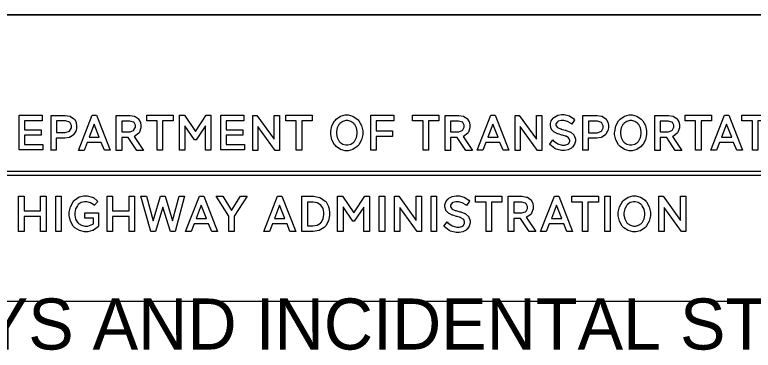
# Model space of a CAD drawing. Extents: x -27.4 to -18.9, y -4.2 to 6.8.
# Drawn here: x -21.647 to -20.305, y -3.032 to -2.423 of the extents above; entities that cross this region are included whole.
import ezdxf

# ---------------------------------------------------------------- set-up
doc = ezdxf.new("R2010")
doc.units = 0
for name, color, linetype in [('BORD-LINE', 7, 'Continuous'), ('MSHA-LOGO', 7, 'Continuous'), ('TTLB-TEXT', 7, 'Continuous'), ('USER-LINE', 7, 'Continuous')]:
    doc.layers.add(name, color=color, linetype=linetype)

msp = doc.modelspace()

# ---------------------------------------------------------------- linework, layer by layer
at = {"layer": 'BORD-LINE'}
msp.add_line((-19.2324, -2.4232), (-23.7053, -2.4232), dxfattribs=at)
at = {"layer": 'MSHA-LOGO'}
for points in [[(-21.639, -2.6056), (-21.5968, -2.6056), (-21.5968, -2.6157), (-21.6292, -2.6157), (-21.6292, -2.6319), (-21.5988, -2.6319), (-21.5988, -2.6417), (-21.6292, -2.6417), (-21.6292, -2.6585), (-21.5958, -2.6585), (-21.5958, -2.6687), (-21.639, -2.6687)], [(-21.5808, -2.6694), (-21.5808, -2.6059), (-21.5579, -2.6059), (-21.555, -2.6059), (-21.5469, -2.6073), (-21.5461, -2.6075), (-21.5453, -2.6078), (-21.5393, -2.612), (-21.5389, -2.6125), (-21.5385, -2.6129), (-21.5355, -2.6185), (-21.5353, -2.619), (-21.5352, -2.6196), (-21.5343, -2.6248), (-21.5343, -2.6266), (-21.5343, -2.6285), (-21.5354, -2.6336), (-21.5356, -2.6342), (-21.5359, -2.6347), (-21.5392, -2.6402), (-21.5396, -2.6407), (-21.54, -2.6412), (-21.5463, -2.6453), (-21.5471, -2.6457), (-21.5479, -2.646), (-21.5556, -2.6473), (-21.5582, -2.6473), (-21.5713, -2.6473), (-21.5713, -2.669), (-21.5808, -2.669)], [(-21.5707, -2.6157), (-21.5707, -2.6371), (-21.5576, -2.6371), (-21.555, -2.6371), (-21.5473, -2.6344), (-21.5438, -2.6283), (-21.5438, -2.6263), (-21.5438, -2.6243), (-21.547, -2.6184), (-21.5544, -2.6157), (-21.5569, -2.6157)], [(-21.5059, -2.6056), (-21.4983, -2.6056), (-21.4734, -2.669), (-21.4839, -2.669), (-21.4895, -2.6552), (-21.5153, -2.6552), (-21.5209, -2.6694), (-21.531, -2.6694)], [(-21.4623, -2.6694), (-21.4623, -2.6059), (-21.4401, -2.6059), (-21.4373, -2.6059), (-21.4298, -2.6073), (-21.4289, -2.6075), (-21.4282, -2.6078), (-21.4225, -2.6116), (-21.4221, -2.6121), (-21.4217, -2.6126), (-21.4187, -2.6178), (-21.4185, -2.6184), (-21.4183, -2.619), (-21.4175, -2.6242), (-21.4175, -2.6259), (-21.4175, -2.6288), (-21.4202, -2.6366), (-21.4208, -2.6375), (-21.4213, -2.6383), (-21.429, -2.644), (-21.4299, -2.6444), (-21.4129, -2.6697), (-21.425, -2.6697), (-21.4404, -2.6463), (-21.4525, -2.6463), (-21.4525, -2.6697), (-21.4623, -2.6697)], [(-21.4522, -2.6161), (-21.4522, -2.6355), (-21.4394, -2.6355), (-21.4372, -2.6355), (-21.4312, -2.6333), (-21.4306, -2.6328), (-21.4301, -2.6324), (-21.4273, -2.6271), (-21.4273, -2.6253), (-21.4273, -2.6236), (-21.4298, -2.6188), (-21.4303, -2.6184), (-21.4308, -2.618), (-21.4375, -2.6161), (-21.4398, -2.6161)], [(-21.407, -2.6056), (-21.3589, -2.6056), (-21.3589, -2.6157), (-21.3782, -2.6157), (-21.3782, -2.669), (-21.388, -2.669), (-21.388, -2.6157), (-21.407, -2.6157)], [(-21.3475, -2.6056), (-21.3386, -2.6056), (-21.3183, -2.6352), (-21.2987, -2.6056), (-21.2902, -2.6056), (-21.2902, -2.669), (-21.3, -2.669), (-21.3, -2.625), (-21.3174, -2.6503), (-21.32, -2.6503), (-21.3376, -2.625), (-21.3376, -2.669), (-21.3475, -2.669)], [(-21.2725, -2.6056), (-21.2303, -2.6056), (-21.2303, -2.6157), (-21.2627, -2.6157), (-21.2627, -2.6319), (-21.2323, -2.6319), (-21.2323, -2.6417), (-21.2627, -2.6417), (-21.2627, -2.6585), (-21.2293, -2.6585), (-21.2293, -2.6687), (-21.2725, -2.6687)], [(-21.1734, -2.6694), (-21.2048, -2.6259), (-21.2048, -2.6694), (-21.2143, -2.6694), (-21.2143, -2.6059), (-21.2067, -2.6059), (-21.1753, -2.6493), (-21.1753, -2.6059), (-21.1658, -2.6059), (-21.1658, -2.6694)], [(-21.1544, -2.6056), (-21.1063, -2.6056), (-21.1063, -2.6157), (-21.1253, -2.6157), (-21.1253, -2.669), (-21.1351, -2.669), (-21.1351, -2.6157), (-21.1541, -2.6157), (-21.1541, -2.6056)], [(-21.0641, -2.6144), (-21.0627, -2.6129), (-21.0548, -2.6073), (-21.0463, -2.6049), (-21.0435, -2.6049), (-21.0407, -2.6049), (-21.0322, -2.6071), (-21.0242, -2.6125), (-21.0228, -2.6141), (-21.0215, -2.6156), (-21.0165, -2.6245), (-21.0143, -2.6342), (-21.0143, -2.6374), (-21.0143, -2.6406), (-21.0165, -2.6502), (-21.0215, -2.6592), (-21.0228, -2.6608), (-21.0242, -2.6624), (-21.0322, -2.6677), (-21.0407, -2.67), (-21.0435, -2.67), (-21.0463, -2.67), (-21.0548, -2.6677), (-21.0627, -2.6624), (-21.0641, -2.6608), (-21.0655, -2.6592), (-21.0704, -2.6504), (-21.0726, -2.6407), (-21.0726, -2.6374), (-21.0726, -2.6343), (-21.0704, -2.6248), (-21.0655, -2.616)], [(-21.0566, -2.6532), (-21.0557, -2.6543), (-21.0505, -2.658), (-21.045, -2.6595), (-21.0431, -2.6595), (-21.0413, -2.6595), (-21.0358, -2.658), (-21.0306, -2.6543), (-21.0297, -2.6532), (-21.0288, -2.6522), (-21.0256, -2.6463), (-21.0242, -2.6397), (-21.0242, -2.6374), (-21.0242, -2.6352), (-21.0256, -2.6285), (-21.0288, -2.6226), (-21.0297, -2.6217), (-21.0306, -2.6206), (-21.0358, -2.6169), (-21.0413, -2.6154), (-21.0431, -2.6154), (-21.045, -2.6154), (-21.0505, -2.6169), (-21.0557, -2.6206), (-21.0566, -2.6217), (-21.0575, -2.6226), (-21.0607, -2.6285), (-21.0621, -2.6352), (-21.0621, -2.6374), (-21.0621, -2.6397), (-21.0608, -2.6463), (-21.0576, -2.6522)], [(-20.9996, -2.6055), (-20.9577, -2.6055), (-20.9577, -2.6157), (-20.9898, -2.6157), (-20.9898, -2.6338), (-20.96, -2.6338), (-20.96, -2.644), (-20.9898, -2.644), (-20.9898, -2.669), (-20.9996, -2.669)], [(-20.924, -2.6055), (-20.8759, -2.6055), (-20.8759, -2.6157), (-20.8949, -2.6157), (-20.8949, -2.669), (-20.9047, -2.669), (-20.9047, -2.6157), (-20.9237, -2.6157), (-20.9237, -2.6055)], [(-20.8645, -2.6694), (-20.8645, -2.6059), (-20.8422, -2.6059), (-20.8394, -2.6059), (-20.8319, -2.6073), (-20.8311, -2.6075), (-20.8304, -2.6078), (-20.8246, -2.6116), (-20.8242, -2.6121), (-20.8238, -2.6126), (-20.8209, -2.6178), (-20.8206, -2.6184), (-20.8204, -2.6189), (-20.8196, -2.6242), (-20.8196, -2.6259), (-20.8196, -2.6288), (-20.8223, -2.6366), (-20.8229, -2.6374), (-20.8235, -2.6383), (-20.8311, -2.644), (-20.8321, -2.6444), (-20.815, -2.6697), (-20.8271, -2.6697), (-20.8425, -2.6463), (-20.8546, -2.6463), (-20.8546, -2.6697), (-20.8645, -2.6697)], [(-20.8546, -2.6161), (-20.8546, -2.6355), (-20.8419, -2.6355), (-20.8397, -2.6355), (-20.8336, -2.6333), (-20.833, -2.6329), (-20.8326, -2.6324), (-20.8298, -2.6271), (-20.8298, -2.6253), (-20.8298, -2.6235), (-20.8322, -2.6188), (-20.8327, -2.6184), (-20.8332, -2.618), (-20.84, -2.6161), (-20.8422, -2.6161)], [(-20.7813, -2.6055), (-20.7738, -2.6055), (-20.7489, -2.669), (-20.7594, -2.669), (-20.765, -2.6549), (-20.7905, -2.6549), (-20.7961, -2.669), (-20.8062, -2.669)], [(-20.6966, -2.6694), (-20.728, -2.6259), (-20.728, -2.6694), (-20.7375, -2.6694), (-20.7375, -2.6059), (-20.73, -2.6059), (-20.6985, -2.6493), (-20.6985, -2.6059), (-20.6891, -2.6059), (-20.6891, -2.6694)], [(-20.6403, -2.647), (-20.6406, -2.6466), (-20.6447, -2.6439), (-20.6452, -2.6437), (-20.6457, -2.6435), (-20.6514, -2.6419), (-20.6521, -2.6417), (-20.6527, -2.6416), (-20.659, -2.6397), (-20.6596, -2.6394), (-20.6603, -2.6392), (-20.666, -2.6365), (-20.6665, -2.6361), (-20.667, -2.6358), (-20.6711, -2.6314), (-20.6714, -2.6309), (-20.6717, -2.6303), (-20.6733, -2.6245), (-20.6733, -2.6226), (-20.6733, -2.6209), (-20.6718, -2.6157), (-20.6682, -2.6107), (-20.6671, -2.6098), (-20.6661, -2.6089), (-20.66, -2.6058), (-20.6533, -2.6045), (-20.6511, -2.6045), (-20.648, -2.6045), (-20.6386, -2.6068), (-20.6305, -2.6122), (-20.6292, -2.6138), (-20.6344, -2.6217), (-20.6356, -2.6206), (-20.6423, -2.6168), (-20.6491, -2.6151), (-20.6514, -2.6151), (-20.6535, -2.6151), (-20.6594, -2.6167), (-20.6599, -2.6171), (-20.6605, -2.6174), (-20.6632, -2.6213), (-20.6632, -2.6226), (-20.6632, -2.6239), (-20.661, -2.6272), (-20.6606, -2.6276), (-20.6602, -2.6279), (-20.6547, -2.6304), (-20.654, -2.6305), (-20.6534, -2.6307), (-20.6463, -2.6326), (-20.6455, -2.6329), (-20.6448, -2.6331), (-20.6377, -2.6358), (-20.637, -2.6361), (-20.6364, -2.6365), (-20.6309, -2.6411), (-20.6305, -2.6417), (-20.6301, -2.6424), (-20.6279, -2.6488), (-20.6279, -2.6509), (-20.6279, -2.6528), (-20.6294, -2.6584), (-20.633, -2.6635), (-20.6341, -2.6644), (-20.6351, -2.6653), (-20.6412, -2.6684), (-20.6474, -2.6697), (-20.6495, -2.6697), (-20.6531, -2.6697), (-20.6627, -2.667), (-20.6639, -2.6664), (-20.665, -2.6658), (-20.674, -2.659), (-20.6746, -2.6582), (-20.6688, -2.6506), (-20.6675, -2.6521), (-20.6599, -2.6574), (-20.6516, -2.6598), (-20.6488, -2.6598), (-20.6468, -2.6598), (-20.6414, -2.6582), (-20.641, -2.6578), (-20.6405, -2.6575), (-20.638, -2.6535), (-20.638, -2.6522), (-20.6381, -2.6517), (-20.64, -2.6473)], [(-20.6141, -2.6694), (-20.6141, -2.6059), (-20.5912, -2.6059), (-20.5883, -2.6059), (-20.5802, -2.6073), (-20.5794, -2.6075), (-20.5786, -2.6078), (-20.5726, -2.6119), (-20.5722, -2.6124), (-20.5718, -2.6129), (-20.5688, -2.6184), (-20.5686, -2.619), (-20.5685, -2.6196), (-20.5676, -2.6248), (-20.5676, -2.6266), (-20.5676, -2.6285), (-20.5687, -2.6336), (-20.569, -2.6342), (-20.5692, -2.6347), (-20.5725, -2.6402), (-20.5729, -2.6407), (-20.5733, -2.6412), (-20.5796, -2.6453), (-20.5804, -2.6457), (-20.5812, -2.646), (-20.589, -2.6473), (-20.5915, -2.6473), (-20.6046, -2.6473), (-20.6046, -2.669), (-20.6141, -2.669)], [(-20.604, -2.6161), (-20.604, -2.6374), (-20.5909, -2.6374), (-20.5883, -2.6374), (-20.5806, -2.6347), (-20.5771, -2.6286), (-20.5771, -2.6266), (-20.5771, -2.6246), (-20.5804, -2.6187), (-20.5878, -2.6161), (-20.5902, -2.6161)], [(-20.548, -2.6144), (-20.5466, -2.6129), (-20.5387, -2.6073), (-20.5302, -2.6049), (-20.5274, -2.6049), (-20.5246, -2.6049), (-20.5161, -2.6071), (-20.5082, -2.6125), (-20.5068, -2.6141), (-20.5054, -2.6156), (-20.5004, -2.6245), (-20.4983, -2.6342), (-20.4983, -2.6374), (-20.4983, -2.6406), (-20.5004, -2.6502), (-20.5054, -2.6592), (-20.5068, -2.6608), (-20.5082, -2.6624), (-20.5161, -2.6677), (-20.5246, -2.67), (-20.5274, -2.67), (-20.5302, -2.67), (-20.5387, -2.6677), (-20.5466, -2.6624), (-20.548, -2.6608), (-20.5494, -2.6592), (-20.5544, -2.6504), (-20.5565, -2.6407), (-20.5565, -2.6374), (-20.5564, -2.6351), (-20.5542, -2.6248), (-20.5494, -2.616)], [(-20.5405, -2.6532), (-20.5396, -2.6543), (-20.5344, -2.658), (-20.5289, -2.6595), (-20.5271, -2.6595), (-20.5252, -2.6595), (-20.5197, -2.658), (-20.5146, -2.6543), (-20.5137, -2.6532), (-20.5128, -2.6522), (-20.5095, -2.6463), (-20.5081, -2.6397), (-20.5081, -2.6374), (-20.5081, -2.6352), (-20.5095, -2.6285), (-20.5128, -2.6226), (-20.5137, -2.6217), (-20.5146, -2.6206), (-20.5197, -2.6169), (-20.5252, -2.6154), (-20.5271, -2.6154), (-20.5289, -2.6154), (-20.5343, -2.6169), (-20.5395, -2.6206), (-20.5405, -2.6217), (-20.5414, -2.6226), (-20.5446, -2.6285), (-20.5461, -2.6352), (-20.5461, -2.6374), (-20.5461, -2.6397), (-20.5448, -2.6463), (-20.5415, -2.6522)], [(-20.4835, -2.6694), (-20.4835, -2.6059), (-20.4613, -2.6059), (-20.4585, -2.6059), (-20.451, -2.6073), (-20.4502, -2.6075), (-20.4494, -2.6078), (-20.4437, -2.6116), (-20.4433, -2.6121), (-20.4429, -2.6126), (-20.4399, -2.6178), (-20.4397, -2.6184), (-20.4395, -2.6189), (-20.4387, -2.6242), (-20.4387, -2.6259), (-20.4387, -2.6288), (-20.4414, -2.6366), (-20.442, -2.6374), (-20.4426, -2.6383), (-20.4502, -2.644), (-20.4511, -2.6444), (-20.4341, -2.6697), (-20.4462, -2.6697), (-20.4616, -2.6463), (-20.4737, -2.6463), (-20.4737, -2.6697), (-20.4835, -2.6697)], [(-20.4737, -2.6161), (-20.4737, -2.6355), (-20.461, -2.6355), (-20.4588, -2.6355), (-20.4527, -2.6333), (-20.4521, -2.6329), (-20.4516, -2.6324), (-20.4488, -2.6271), (-20.4488, -2.6253), (-20.4488, -2.6235), (-20.4513, -2.6188), (-20.4518, -2.6184), (-20.4523, -2.618), (-20.459, -2.6161), (-20.4613, -2.6161)], [(-20.4286, -2.6055), (-20.3804, -2.6055), (-20.3804, -2.6157), (-20.3994, -2.6157), (-20.3994, -2.669), (-20.4093, -2.669), (-20.4093, -2.6157), (-20.4282, -2.6157), (-20.4282, -2.6055)], [(-20.3566, -2.6055), (-20.349, -2.6055), (-20.3242, -2.669), (-20.3346, -2.669), (-20.3402, -2.6549), (-20.3661, -2.6549), (-20.3716, -2.669), (-20.3814, -2.669)], [(-20.3255, -2.6055), (-20.2774, -2.6055), (-20.2774, -2.6157), (-20.2964, -2.6157), (-20.2964, -2.669), (-20.3062, -2.669), (-20.3062, -2.6157), (-20.3252, -2.6157), (-20.3252, -2.6055)], [(-21.5118, -2.6457), (-21.4931, -2.6457), (-21.5026, -2.6217)], [(-20.7869, -2.6457), (-20.7682, -2.6457), (-20.7777, -2.6217)], [(-20.3624, -2.6457), (-20.3438, -2.6457), (-20.3533, -2.6217)], [(-22.2362, -2.7073), (-20.1195, -2.7073), (-20.1195, -2.7152), (-22.2362, -2.7152)], [(-21.5999, -2.7898), (-21.6299, -2.7898), (-21.6299, -2.8171), (-21.6398, -2.8171), (-21.6398, -2.7528), (-21.6299, -2.7528), (-21.6299, -2.7795), (-21.5999, -2.7795), (-21.5999, -2.7528), (-21.59, -2.7528), (-21.59, -2.8171), (-21.5999, -2.8171)], [(-21.5724, -2.7528), (-21.5625, -2.7528), (-21.5625, -2.8171), (-21.5724, -2.8171)], [(-21.5194, -2.7827), (-21.4945, -2.7827), (-21.4945, -2.8074), (-21.4951, -2.8082), (-21.5034, -2.8144), (-21.5044, -2.8148), (-21.5054, -2.8153), (-21.5142, -2.8174), (-21.5171, -2.8174), (-21.5202, -2.8174), (-21.5294, -2.8152), (-21.5378, -2.8099), (-21.5392, -2.8084), (-21.5406, -2.8069), (-21.5457, -2.798), (-21.5478, -2.788), (-21.5478, -2.7846), (-21.5478, -2.7814), (-21.5457, -2.7718), (-21.5409, -2.7628), (-21.5395, -2.7612), (-21.5381, -2.7596), (-21.5299, -2.7541), (-21.5213, -2.7519), (-21.5184, -2.7519), (-21.5151, -2.7519), (-21.506, -2.7543), (-21.505, -2.7548), (-21.504, -2.7552), (-21.4963, -2.7617), (-21.4957, -2.7625), (-21.5024, -2.7695), (-21.5033, -2.7684), (-21.5089, -2.7645), (-21.5156, -2.7628), (-21.5178, -2.7628), (-21.5198, -2.7628), (-21.5259, -2.7643), (-21.5313, -2.7679), (-21.5321, -2.7689), (-21.533, -2.7699), (-21.5362, -2.7758), (-21.5376, -2.7827), (-21.5376, -2.785), (-21.5376, -2.7873), (-21.5362, -2.7942), (-21.5328, -2.8003), (-21.5318, -2.8013), (-21.5309, -2.8023), (-21.5253, -2.8056), (-21.5192, -2.8071), (-21.5171, -2.8071), (-21.5139, -2.8071), (-21.5049, -2.8033), (-21.504, -2.8026), (-21.504, -2.7927), (-21.5194, -2.7927)], [(-21.4389, -2.7898), (-21.4689, -2.7898), (-21.4689, -2.8171), (-21.4788, -2.8171), (-21.4788, -2.7528), (-21.4689, -2.7528), (-21.4689, -2.7795), (-21.4389, -2.7795), (-21.4389, -2.7528), (-21.429, -2.7528), (-21.429, -2.8171), (-21.4389, -2.8171)], [(-21.3552, -2.8171), (-21.3635, -2.8171), (-21.3775, -2.7724), (-21.3912, -2.8171), (-21.3995, -2.8171), (-21.4175, -2.7528), (-21.4072, -2.7528), (-21.3951, -2.7972), (-21.3817, -2.7528), (-21.3737, -2.7528), (-21.3599, -2.7972), (-21.3481, -2.7528), (-21.3382, -2.7528)], [(-21.3111, -2.7528), (-21.3034, -2.7528), (-21.2781, -2.8171), (-21.2887, -2.8171), (-21.2944, -2.8029), (-21.3206, -2.8029), (-21.3261, -2.8171), (-21.3363, -2.8171)], [(-21.2481, -2.7891), (-21.2481, -2.8171), (-21.258, -2.8171), (-21.258, -2.7891), (-21.281, -2.7528), (-21.2685, -2.7528), (-21.2526, -2.7785), (-21.2363, -2.7528), (-21.2245, -2.7528)], [(-21.169, -2.7528), (-21.1613, -2.7528), (-21.1361, -2.8171), (-21.1466, -2.8171), (-21.152, -2.8029), (-21.1782, -2.8029), (-21.1837, -2.8171), (-21.1939, -2.8171)], [(-21.1249, -2.7528), (-21.107, -2.7528), (-21.1032, -2.7528), (-21.093, -2.755), (-21.092, -2.7554), (-21.0909, -2.7558), (-21.0824, -2.7617), (-21.0817, -2.7625), (-21.0811, -2.7632), (-21.0766, -2.7715), (-21.0763, -2.7724), (-21.076, -2.7734), (-21.0747, -2.7816), (-21.0747, -2.7843), (-21.0747, -2.7876), (-21.0768, -2.7975), (-21.0817, -2.8065), (-21.083, -2.8081), (-21.0844, -2.8096), (-21.0934, -2.8148), (-21.1043, -2.8171), (-21.1079, -2.8171), (-21.1249, -2.8171)], [(-21.115, -2.7634), (-21.115, -2.8068), (-21.1073, -2.8068), (-21.1048, -2.8068), (-21.0974, -2.8053), (-21.0913, -2.8017), (-21.0904, -2.8007), (-21.0894, -2.7996), (-21.0862, -2.7935), (-21.0849, -2.7866), (-21.0849, -2.7843), (-21.0849, -2.782), (-21.0863, -2.7752), (-21.0905, -2.7687), (-21.0974, -2.7647), (-21.1046, -2.7634), (-21.107, -2.7634)], [(-21.06, -2.7528), (-21.0511, -2.7528), (-21.0306, -2.7827), (-21.0108, -2.7528), (-21.0022, -2.7528), (-21.0022, -2.8171), (-21.0121, -2.8171), (-21.0121, -2.7724), (-21.0297, -2.7978), (-21.0322, -2.7978), (-21.0501, -2.7721), (-21.0501, -2.8167), (-21.06, -2.8167)], [(-20.9843, -2.7528), (-20.9744, -2.7528), (-20.9744, -2.8171), (-20.9843, -2.8171)], [(-20.9153, -2.8171), (-20.9469, -2.7734), (-20.9469, -2.8171), (-20.9565, -2.8171), (-20.9565, -2.7528), (-20.9488, -2.7528), (-20.9172, -2.7968), (-20.9172, -2.7528), (-20.9076, -2.7528), (-20.9076, -2.8171)], [(-20.89, -2.7528), (-20.8801, -2.7528), (-20.8801, -2.8171), (-20.89, -2.8171)], [(-20.8312, -2.7949), (-20.8316, -2.7946), (-20.8358, -2.7919), (-20.8364, -2.7917), (-20.8369, -2.7915), (-20.8428, -2.7896), (-20.8434, -2.7894), (-20.844, -2.7893), (-20.8504, -2.7874), (-20.8511, -2.7872), (-20.8517, -2.787), (-20.8575, -2.7843), (-20.8581, -2.784), (-20.8587, -2.7837), (-20.8629, -2.7791), (-20.8632, -2.7785), (-20.8635, -2.778), (-20.8651, -2.7721), (-20.8651, -2.7702), (-20.8651, -2.7684), (-20.8635, -2.7632), (-20.8598, -2.7582), (-20.8587, -2.7573), (-20.8577, -2.7564), (-20.8516, -2.7534), (-20.8447, -2.7522), (-20.8424, -2.7522), (-20.8393, -2.7522), (-20.8297, -2.7546), (-20.8214, -2.76), (-20.8201, -2.7615), (-20.8255, -2.7695), (-20.8267, -2.7684), (-20.8334, -2.7645), (-20.8404, -2.7628), (-20.8427, -2.7628), (-20.8449, -2.7628), (-20.8508, -2.7644), (-20.8514, -2.7647), (-20.8519, -2.765), (-20.8549, -2.7691), (-20.8549, -2.7705), (-20.8549, -2.7718), (-20.8527, -2.7752), (-20.8523, -2.7756), (-20.8519, -2.776), (-20.8464, -2.7784), (-20.8456, -2.7785), (-20.8449, -2.7787), (-20.8378, -2.7808), (-20.837, -2.7811), (-20.8362, -2.7813), (-20.829, -2.7841), (-20.8284, -2.7843), (-20.8277, -2.7846), (-20.8221, -2.7894), (-20.8217, -2.7901), (-20.8213, -2.7907), (-20.8191, -2.7972), (-20.8191, -2.7994), (-20.8191, -2.8013), (-20.8207, -2.807), (-20.8245, -2.8123), (-20.8255, -2.8132), (-20.8265, -2.8141), (-20.8326, -2.8173), (-20.839, -2.8187), (-20.8411, -2.8187), (-20.8448, -2.8187), (-20.8546, -2.816), (-20.8558, -2.8155), (-20.857, -2.8149), (-20.8661, -2.8079), (-20.8667, -2.8071), (-20.8606, -2.7994), (-20.8594, -2.8009), (-20.8517, -2.8063), (-20.8431, -2.8087), (-20.8402, -2.8087), (-20.8382, -2.8087), (-20.8327, -2.8071), (-20.8322, -2.8068), (-20.8317, -2.8065), (-20.8293, -2.8024), (-20.8293, -2.801), (-20.8293, -2.7995), (-20.8309, -2.7952)], [(-20.8099, -2.7528), (-20.7613, -2.7528), (-20.7613, -2.7634), (-20.7804, -2.7634), (-20.7804, -2.8171), (-20.7903, -2.8171), (-20.7903, -2.7634), (-20.8095, -2.7634), (-20.8095, -2.7528)], [(-20.7498, -2.8171), (-20.7498, -2.7528), (-20.7271, -2.7528), (-20.7243, -2.7528), (-20.7167, -2.7542), (-20.7159, -2.7545), (-20.7151, -2.7547), (-20.7093, -2.7585), (-20.7089, -2.7589), (-20.7085, -2.7594), (-20.7055, -2.7648), (-20.7054, -2.7654), (-20.7052, -2.7659), (-20.7044, -2.771), (-20.7044, -2.7728), (-20.7044, -2.7756), (-20.7074, -2.7835), (-20.7079, -2.7843), (-20.7085, -2.7851), (-20.7162, -2.7908), (-20.7172, -2.791), (-20.6999, -2.8167), (-20.7121, -2.8167), (-20.7277, -2.7933), (-20.7399, -2.7933), (-20.7399, -2.8167), (-20.7498, -2.8167)], [(-20.7399, -2.7634), (-20.7399, -2.783), (-20.7271, -2.783), (-20.7249, -2.783), (-20.7187, -2.7809), (-20.7181, -2.7805), (-20.7176, -2.78), (-20.7149, -2.7748), (-20.7149, -2.7731), (-20.7149, -2.7713), (-20.7174, -2.7664), (-20.7178, -2.766), (-20.7183, -2.7656), (-20.7251, -2.7634), (-20.7274, -2.7634)], [(-20.6657, -2.7528), (-20.6581, -2.7528), (-20.6328, -2.8171), (-20.6434, -2.8171), (-20.6491, -2.8029), (-20.6753, -2.8029), (-20.6808, -2.8171), (-20.691, -2.8171)], [(-20.6344, -2.7528), (-20.5859, -2.7528), (-20.5859, -2.7634), (-20.605, -2.7634), (-20.605, -2.8171), (-20.6149, -2.8171), (-20.6149, -2.7634), (-20.6341, -2.7634), (-20.6341, -2.7528)], [(-20.5744, -2.7528), (-20.5645, -2.7528), (-20.5645, -2.8171), (-20.5744, -2.8171)], [(-20.5415, -2.7618), (-20.54, -2.7602), (-20.5319, -2.7546), (-20.5235, -2.7522), (-20.5207, -2.7522), (-20.5179, -2.7522), (-20.5094, -2.7546), (-20.5013, -2.76), (-20.4999, -2.7615), (-20.4986, -2.763), (-20.4936, -2.772), (-20.4913, -2.7817), (-20.4913, -2.785), (-20.4913, -2.7882), (-20.4935, -2.7978), (-20.4985, -2.8068), (-20.4999, -2.8084), (-20.5014, -2.81), (-20.5095, -2.8154), (-20.5179, -2.8177), (-20.5207, -2.8177), (-20.5236, -2.8177), (-20.5322, -2.8153), (-20.5401, -2.8099), (-20.5415, -2.8084), (-20.5429, -2.8069), (-20.5479, -2.7979), (-20.5501, -2.7882), (-20.5501, -2.785), (-20.5501, -2.7818), (-20.5479, -2.7723), (-20.5429, -2.7634)], [(-20.5341, -2.801), (-20.5332, -2.8021), (-20.5279, -2.8056), (-20.5225, -2.8071), (-20.5207, -2.8071), (-20.5188, -2.8071), (-20.5132, -2.8056), (-20.5079, -2.8021), (-20.5069, -2.801), (-20.506, -2.8), (-20.5028, -2.7939), (-20.5015, -2.7872), (-20.5015, -2.785), (-20.5015, -2.7827), (-20.503, -2.7761), (-20.5063, -2.7699), (-20.5073, -2.7689), (-20.5082, -2.7679), (-20.5135, -2.7643), (-20.5189, -2.7628), (-20.5207, -2.7628), (-20.5225, -2.7628), (-20.528, -2.7643), (-20.5332, -2.7679), (-20.5341, -2.7689), (-20.535, -2.7699), (-20.5381, -2.7759), (-20.5395, -2.7827), (-20.5395, -2.785), (-20.5395, -2.7872), (-20.5381, -2.7939), (-20.535, -2.8)], [(-20.4351, -2.8171), (-20.4667, -2.7734), (-20.4667, -2.8171), (-20.4763, -2.8171), (-20.4763, -2.7528), (-20.4686, -2.7528), (-20.437, -2.7968), (-20.437, -2.7528), (-20.4274, -2.7528), (-20.4274, -2.8171)], [(-21.3171, -2.7933), (-21.2983, -2.7933), (-21.3079, -2.7689)], [(-21.1747, -2.7933), (-21.1559, -2.7933), (-21.1655, -2.7689)], [(-20.6715, -2.7933), (-20.6526, -2.7933), (-20.6622, -2.7689)]]:
    msp.add_lwpolyline(points, close=True, dxfattribs=at)
at = {"layer": 'USER-LINE'}
msp.add_lwpolyline([(-19.9833, -2.9439), (-22.9545, -2.9439), (-22.9545, -2.4232), (-19.9833, -2.4232)], close=True, dxfattribs=at)

# ---------------------------------------------------------------- texts
at = {"layer": 'TTLB-TEXT'}
msp.add_text('STANDARDS FOR HIGHWAYS AND INCIDENTAL STRUCTURES', height=0.09269, dxfattribs=at).set_placement((-23.3095, -3.0312))

doc.saveas('drawing.dxf')
